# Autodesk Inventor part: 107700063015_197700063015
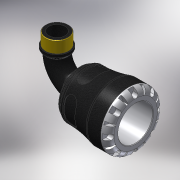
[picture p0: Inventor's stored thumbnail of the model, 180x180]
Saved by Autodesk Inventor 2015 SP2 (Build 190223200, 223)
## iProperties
Created: 2016-12
Part Number: 107700063015_197700063015
Material: PVC-Piping
Description: PLASSON 90° ELBOW WITH MALE INTEGRAL BRASS 63X1.1/2" SERIES 1
Document SubType Name: Modeling
Designer: KIM
Mass: 664.223 g
Surface Area: 733.008 cm^2
Volume: 474.445 cm^3
Density: 1.4 g/cm^3
Appearance: Black Cast
Author: KIM
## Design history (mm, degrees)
derived "1077.ipt"
feature "Solid1::1077.ipt"
tag "TaggingFeature1"
body "Solid1"
other parameters: "d1" = 37.8, "d2" = 63, "d3" = 78.75, "d4" = 103, "d8" = 87.55, "d13" = 9.7, "d14" = 9.7, "d15" = 0, "d17" = 360 deg, "d19" = 8 deg, "d20" = 1.26, "d21" = 1.26, "d22" = 8 deg, "d24" = 0, "d26" = 360 deg, "d33" = 10.3, "d43" = 80.34, "d51" = 1.03, "d54" = 22.05, "d55" = 13.86, "d57" = 19.012, "d58" = 0, "d74" = 0, "d82" = 1.26, "d115" = 360 deg, "d207" = 90 deg, "d228" = 18.7425, "d247" = 2.06, "d248" = 5.4, "d268" = 48.1525, "d269" = 5.4, "d270" = 143, "d276" = 47.803, "d277" = 21, "d278" = 52.5833, "d279" = 74, "d280" = 27.3, "d281" = 7.17045, "d283" = 43.0227, "d286" = 0, "d287" = 0, "d288" = 33.4621, "d290" = 18.65865, "d292" = 30 deg, "d294" = 4.7803, "d296" = 30 deg, "d_" = 63, "E_" = 103, "A_" = 143, "A_1" = 74, "l_2" = 21, "R_" = 47.803, "d9" = 12.125, "d11" = 103, "d12" = 78.75, "d289" = 33.4621
